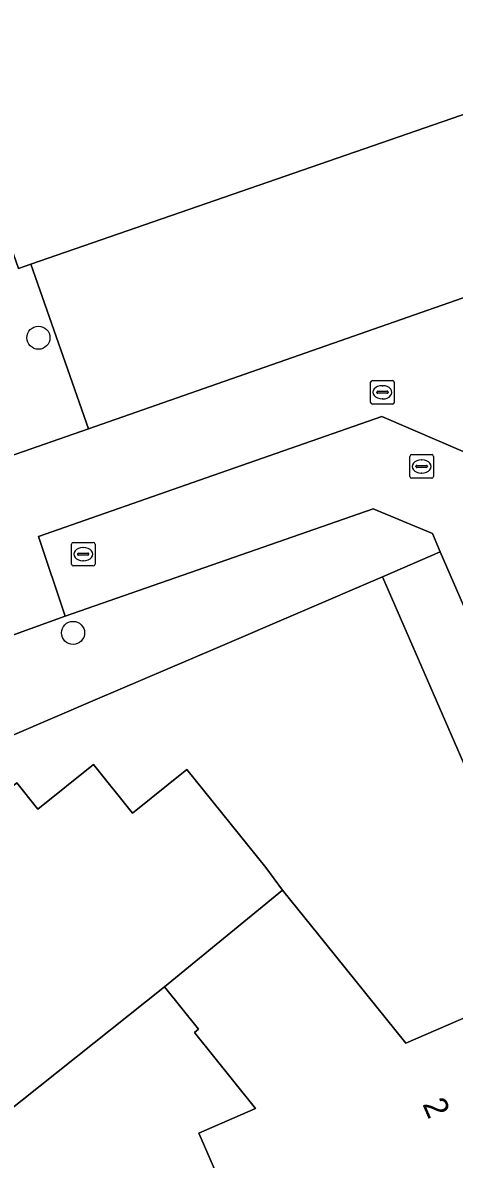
# Model space of a CAD drawing. Extents: x 158472 to 159562, y 388525 to 389606.
# Drawn here: x 158918.1 to 158936.4, y 388971.09 to 389019.31 of the extents above; entities that cross this region are included whole.
import ezdxf

# ---------------------------------------------------------------- set-up
doc = ezdxf.new("R2010")
doc.units = 0
for name, color, linetype in [('IMGEO_Boom', 7, 'Continuous'), ('IMGEO_Erf', 7, 'Continuous'), ('IMGEO_Groenvoorziening', 7, 'Continuous'), ('IMGEO_Hek', 7, 'Continuous'), ('IMGEO_Kolk', 7, 'Continuous'), ('IMGEO_Pand', 7, 'Continuous'), ('IMGEO_Pand_nummerreeks', 7, 'Continuous'), ('IMGEO_Parkeervlak_open', 7, 'Continuous'), ('IMGEO_Rijbaan_lokaal_open', 7, 'Continuous'), ('IMGEO_Rioolput', 7, 'Continuous'), ('IMGEO_Voetpad_open', 7, 'Continuous')]:
    doc.layers.add(name, color=color, linetype=linetype)

msp = doc.modelspace()

# ---------------------------------------------------------------- linework, layer by layer
at = {"layer": 'IMGEO_Boom'}
for centre in [(158918.766, 389005.943), (158920.234, 388993.421)]:
    msp.add_circle(centre, 0.489, dxfattribs=at)
at = {"layer": 'IMGEO_Erf'}
for points in [[(158909.555, 389032.805), (158917.921, 389008.881), (158918.44, 389009.061), (158941.853, 389017.161), (158943.711, 389011.826), (158945.956, 389010.85), (158955.619, 389014.231), (158972.864, 389020.265)], [(158982.198, 388910.573), (158963.265, 388927.1), (158940.226, 388980.021), (158933.359, 388995.794), (158926.282, 388992.761), (158921.177, 388990.574), (158910.593, 388986.04), (158887.292, 388967.121)], [(158886.895, 388966.813), (158890.654, 388962.284), (158891.774, 388963.184), (158896.353, 388966.866), (158900.838, 388970.472), (158905.416, 388974.153), (158909.499, 388977.436), (158908.546, 388978.621), (158908.903, 388978.908), (158909.305, 388978.408), (158912.153, 388980.698), (158913.634, 388981.889), (158915.781, 388983.615), (158914.907, 388984.701), (158917.844, 388987.063), (158918.741, 388985.947), (158921.094, 388987.839), (158922.756, 388985.772), (158925.059, 388987.624), (158928.406, 388983.461), (158929.121, 388982.51), (158930.96, 388980.222), (158934.346, 388976.009), (158936.992, 388977.163)], [(158927.347, 388968.112), (158925.566, 388972.196), (158927.976, 388973.246), (158925.386, 388976.467), (158925.561, 388976.608), (158924.117, 388978.405), (158915.075, 388971.226), (158912.056, 388968.798)]]:
    msp.add_lwpolyline(points, dxfattribs=at)
at = {"layer": 'IMGEO_Groenvoorziening'}
msp.add_lwpolyline([(158909.555, 389032.805), (158906.675, 389031.798), (158915.039, 389007.876), (158917.483, 389000.888), (158920.882, 389002.077), (158918.44, 389009.061), (158917.921, 389008.881)], close=True, dxfattribs=at)
at = {"layer": 'IMGEO_Hek'}
msp.add_lwpolyline([(158918.44, 389009.061), (158941.853, 389017.161), (158943.711, 389011.826), (158945.956, 389010.85)], dxfattribs=at)
at = {"layer": 'IMGEO_Kolk'}
for p, q in [((158934.519, 389000.056), (158934.519, 389000.908)), ((158934.594, 389000.982), (158935.446, 389000.982)), ((158935.007, 389000.762), (158935.032, 389000.762)), ((158935.52, 389000.908), (158935.52, 389000.056)), ((158934.778, 389000.476), (158934.778, 389000.488)), ((158935.216, 389000.439), (158934.818, 389000.439)), ((158934.821, 389000.525), (158935.219, 389000.525)), ((158935.03, 389000.202), (158935.005, 389000.202)), ((158935.262, 389000.488), (158935.262, 389000.476)), ((158935.446, 388999.982), (158934.594, 388999.982)), ((158920.166, 388996.334), (158920.166, 388997.186)), ((158920.241, 388997.26), (158921.093, 388997.26)), ((158920.468, 388996.803), (158920.866, 388996.803)), ((158920.654, 388997.04), (158920.679, 388997.04)), ((158921.167, 388997.186), (158921.167, 388996.334)), ((158920.425, 388996.754), (158920.425, 388996.766)), ((158920.863, 388996.717), (158920.465, 388996.717)), ((158920.677, 388996.48), (158920.652, 388996.48)), ((158920.909, 388996.766), (158920.909, 388996.754)), ((158921.093, 388996.26), (158920.241, 388996.26))]:
    msp.add_line(p, q, dxfattribs=at)
for points in [[(158934.519, 389000.056), (158934.519, 389000.908)], [(158934.594, 389000.982), (158935.446, 389000.982)], [(158935.52, 389000.908), (158935.52, 389000.056)], [(158935.446, 388999.982), (158934.594, 388999.982)], [(158920.166, 388996.334), (158920.166, 388997.186)], [(158920.241, 388997.26), (158921.093, 388997.26)], [(158921.167, 388997.186), (158921.167, 388996.334)], [(158921.093, 388996.26), (158920.241, 388996.26)]]:
    msp.add_lwpolyline(points, dxfattribs=at)
for centre, radius, start, end in [((158934.596, 389000.906), 0.0765, 91.552, 178.448), ((158934.596, 389000.906), 0.0765, 91.552, 178.448), ((158935.444, 389000.906), 0.0765, 1.552, 88.448), ((158935.444, 389000.906), 0.0765, 1.552, 88.448), ((158934.818, 389000.485), 0.0403, 85.8775, 175.7526), ((158934.815, 389000.475), 0.0366, 178.938, 274.7102), ((158935.219, 389000.482), 0.043, 264.8664, 352.4533), ((158935.223, 389000.487), 0.0386, 1.7309, 96.639), ((158934.596, 389000.058), 0.0765, 181.552, 268.448), ((158934.596, 389000.058), 0.0765, 181.552, 268.448), ((158935.444, 389000.058), 0.0765, 271.552, 358.448), ((158935.444, 389000.058), 0.0765, 271.552, 358.448), ((158920.243, 388997.184), 0.0765, 91.552, 178.448), ((158920.243, 388997.184), 0.0765, 91.552, 178.448), ((158920.465, 388996.763), 0.0403, 85.8775, 175.7526), ((158920.87, 388996.765), 0.0386, 1.7309, 96.639), ((158921.091, 388997.184), 0.0765, 1.552, 88.448), ((158921.091, 388997.184), 0.0765, 1.552, 88.448), ((158920.243, 388996.336), 0.0765, 181.552, 268.448), ((158920.243, 388996.336), 0.0765, 181.552, 268.448), ((158920.462, 388996.753), 0.0366, 178.938, 274.7102), ((158920.866, 388996.76), 0.043, 264.8664, 352.4533), ((158921.091, 388996.336), 0.0765, 271.552, 358.448), ((158921.091, 388996.336), 0.0765, 271.552, 358.448)]:
    msp.add_arc(centre, radius, start, end, dxfattribs=at)
for centre, major_axis, ratio, start_param, end_param in [((158935.006, 389000.482), (-0.387, 0.002), 0.722429, 4.712389, 7.853982), ((158935.031, 389000.482), (-0.39, 0.002), 0.717154, 1.570796, 4.712389), ((158920.653, 388996.76), (-0.387, 0.002), 0.722429, 4.712389, 7.853982), ((158920.678, 388996.76), (-0.39, 0.002), 0.717154, 1.570796, 4.712389)]:
    msp.add_ellipse(centre, major_axis=major_axis, ratio=ratio, start_param=start_param, end_param=end_param, dxfattribs=at)
at = {"layer": 'IMGEO_Pand'}
for points in [[(158929.121, 388982.51), (158928.406, 388983.461), (158925.059, 388987.624), (158922.756, 388985.772), (158921.094, 388987.839), (158918.741, 388985.947), (158917.844, 388987.063), (158914.907, 388984.701), (158915.781, 388983.615), (158913.634, 388981.889), (158912.153, 388980.698), (158909.305, 388978.408), (158915.075, 388971.226), (158924.117, 388978.405)], [(158936.992, 388977.163), (158934.346, 388976.009), (158930.96, 388980.222), (158929.121, 388982.51), (158924.117, 388978.405), (158925.561, 388976.608), (158925.386, 388976.467), (158927.976, 388973.246), (158925.566, 388972.196), (158927.347, 388968.112), (158927.906, 388966.829), (158928.012, 388966.587), (158929.872, 388967.398), (158929.766, 388967.64), (158938.528, 388971.46), (158939.327, 388971.808)]]:
    msp.add_lwpolyline(points, close=True, dxfattribs=at)
at = {"layer": 'IMGEO_Parkeervlak_open'}
msp.add_lwpolyline([(158945.956, 389010.85), (158943.711, 389011.826), (158941.853, 389017.161), (158918.44, 389009.061), (158920.882, 389002.077)], close=True, dxfattribs=at)
at = {"layer": 'IMGEO_Rijbaan_lokaal_open'}
msp.add_lwpolyline([(158946.141, 388982.191), (158945.844, 388982.877), (158938.341, 389000), (158938.099, 389000.552), (158933.327, 389002.602), (158925.886, 389000), (158918.768, 388997.511), (158919.894, 388994.128), (158932.967, 388998.688), (158935.473, 388997.636), (158935.81, 388996.86), (158949.356, 388965.698), (158965.417, 388928.842), (158973.375, 388921.798), (158978.193, 388927.225)], dxfattribs=at)
at = {"layer": 'IMGEO_Rioolput'}
for p, q in [((158932.855, 389003.202), (158932.855, 389004.054)), ((158932.93, 389004.128), (158933.782, 389004.128)), ((158933.856, 389004.054), (158933.856, 389003.202)), ((158933.114, 389003.622), (158933.114, 389003.634)), ((158933.552, 389003.585), (158933.154, 389003.585)), ((158933.157, 389003.671), (158933.555, 389003.671)), ((158933.343, 389003.908), (158933.368, 389003.908)), ((158933.598, 389003.634), (158933.598, 389003.622)), ((158933.782, 389003.128), (158932.93, 389003.128)), ((158933.366, 389003.348), (158933.341, 389003.348))]:
    msp.add_line(p, q, dxfattribs=at)
for points in [[(158932.855, 389003.202), (158932.855, 389004.054)], [(158932.93, 389004.128), (158933.782, 389004.128)], [(158933.856, 389004.054), (158933.856, 389003.202)], [(158933.782, 389003.128), (158932.93, 389003.128)]]:
    msp.add_lwpolyline(points, dxfattribs=at)
for centre, radius, start, end in [((158932.932, 389004.052), 0.0765, 91.552, 178.448), ((158932.932, 389004.052), 0.0765, 91.552, 178.448), ((158933.78, 389004.052), 0.0765, 1.552, 88.448), ((158933.78, 389004.052), 0.0765, 1.552, 88.448), ((158933.154, 389003.631), 0.0403, 85.8775, 175.7526), ((158933.151, 389003.621), 0.0366, 178.938, 274.7102), ((158933.555, 389003.628), 0.043, 264.8664, 352.4533), ((158933.559, 389003.633), 0.0386, 1.7309, 96.639), ((158932.932, 389003.204), 0.0765, 181.552, 268.448), ((158932.932, 389003.204), 0.0765, 181.552, 268.448), ((158933.78, 389003.204), 0.0765, 271.552, 358.448), ((158933.78, 389003.204), 0.0765, 271.552, 358.448)]:
    msp.add_arc(centre, radius, start, end, dxfattribs=at)
for centre, major_axis, ratio, start_param, end_param in [((158933.342, 389003.628), (-0.387, 0.002), 0.722429, 4.712389, 7.853982), ((158933.367, 389003.628), (-0.39, 0.002), 0.717154, 1.570796, 4.712389)]:
    msp.add_ellipse(centre, major_axis=major_axis, ratio=ratio, start_param=start_param, end_param=end_param, dxfattribs=at)
at = {"layer": 'IMGEO_Voetpad_open'}
for points in [[(158972.864, 389020.265), (158955.619, 389014.231), (158945.956, 389010.85), (158920.882, 389002.077), (158917.483, 389000.888), (158915.039, 389007.876), (158906.675, 389031.798)], [(158925.886, 389000), (158933.327, 389002.602), (158938.099, 389000.552), (158940.053, 389004.745), (158945.596, 389006.687), (158957.099, 389010.716), (158962.933, 389012.76), (158983.138, 389019.838)], [(158911.951, 388991.266), (158919.894, 388994.128), (158918.768, 388997.511), (158925.886, 389000)], [(158887.292, 388967.121), (158910.593, 388986.04), (158921.177, 388990.574), (158926.282, 388992.761), (158933.359, 388995.794), (158935.81, 388996.86), (158935.473, 388997.636), (158932.967, 388998.688), (158919.894, 388994.128), (158911.951, 388991.266), (158911.228, 388992.014), (158910.758, 388991.597), (158908.446, 388989.723)], [(158949.356, 388965.698), (158935.81, 388996.86), (158933.359, 388995.794), (158940.226, 388980.021), (158963.265, 388927.1), (158982.198, 388910.573), (158983.711, 388912.434), (158982.25, 388913.851), (158982.208, 388914.236), (158982.016, 388914.335), (158981.86, 388920.424), (158981.993, 388921.419), (158982.824, 388923.338), (158987.372, 388928.478), (158987.5, 388928.773)]]:
    msp.add_lwpolyline(points, dxfattribs=at)

# ---------------------------------------------------------------- texts
at = {"layer": 'IMGEO_Pand_nummerreeks'}
msp.add_text('2', height=1, rotation=293.5598, dxfattribs=at).set_placement((158935.042, 388973.429))

doc.saveas('drawing.dxf')
